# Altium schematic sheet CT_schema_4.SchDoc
size 573 x 363 mm
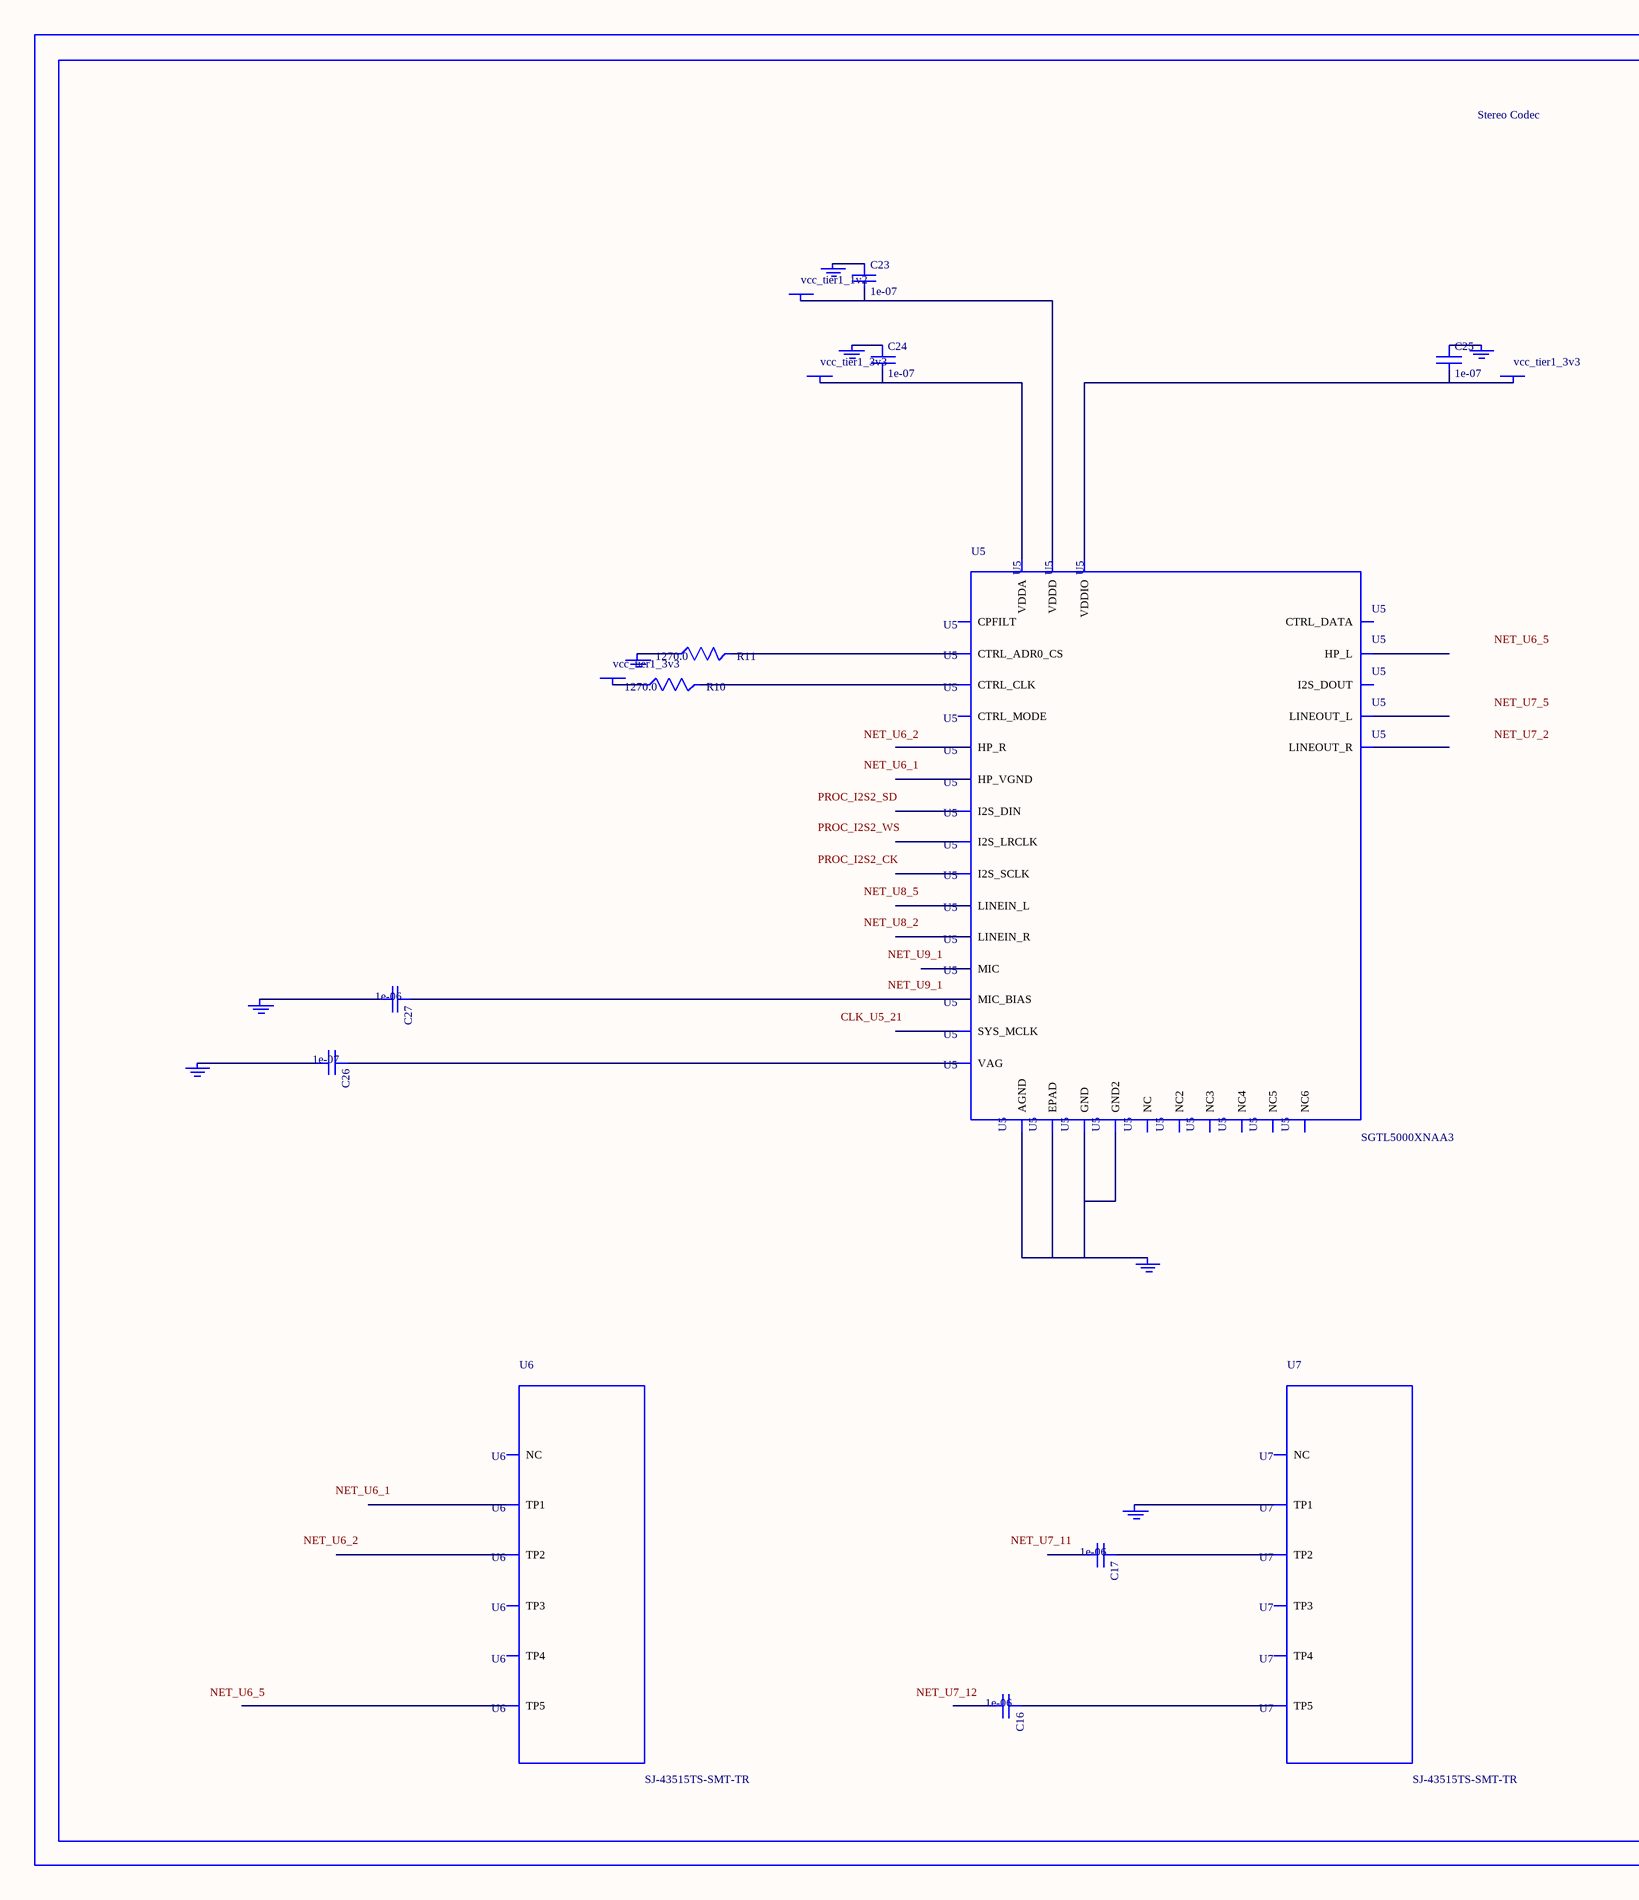
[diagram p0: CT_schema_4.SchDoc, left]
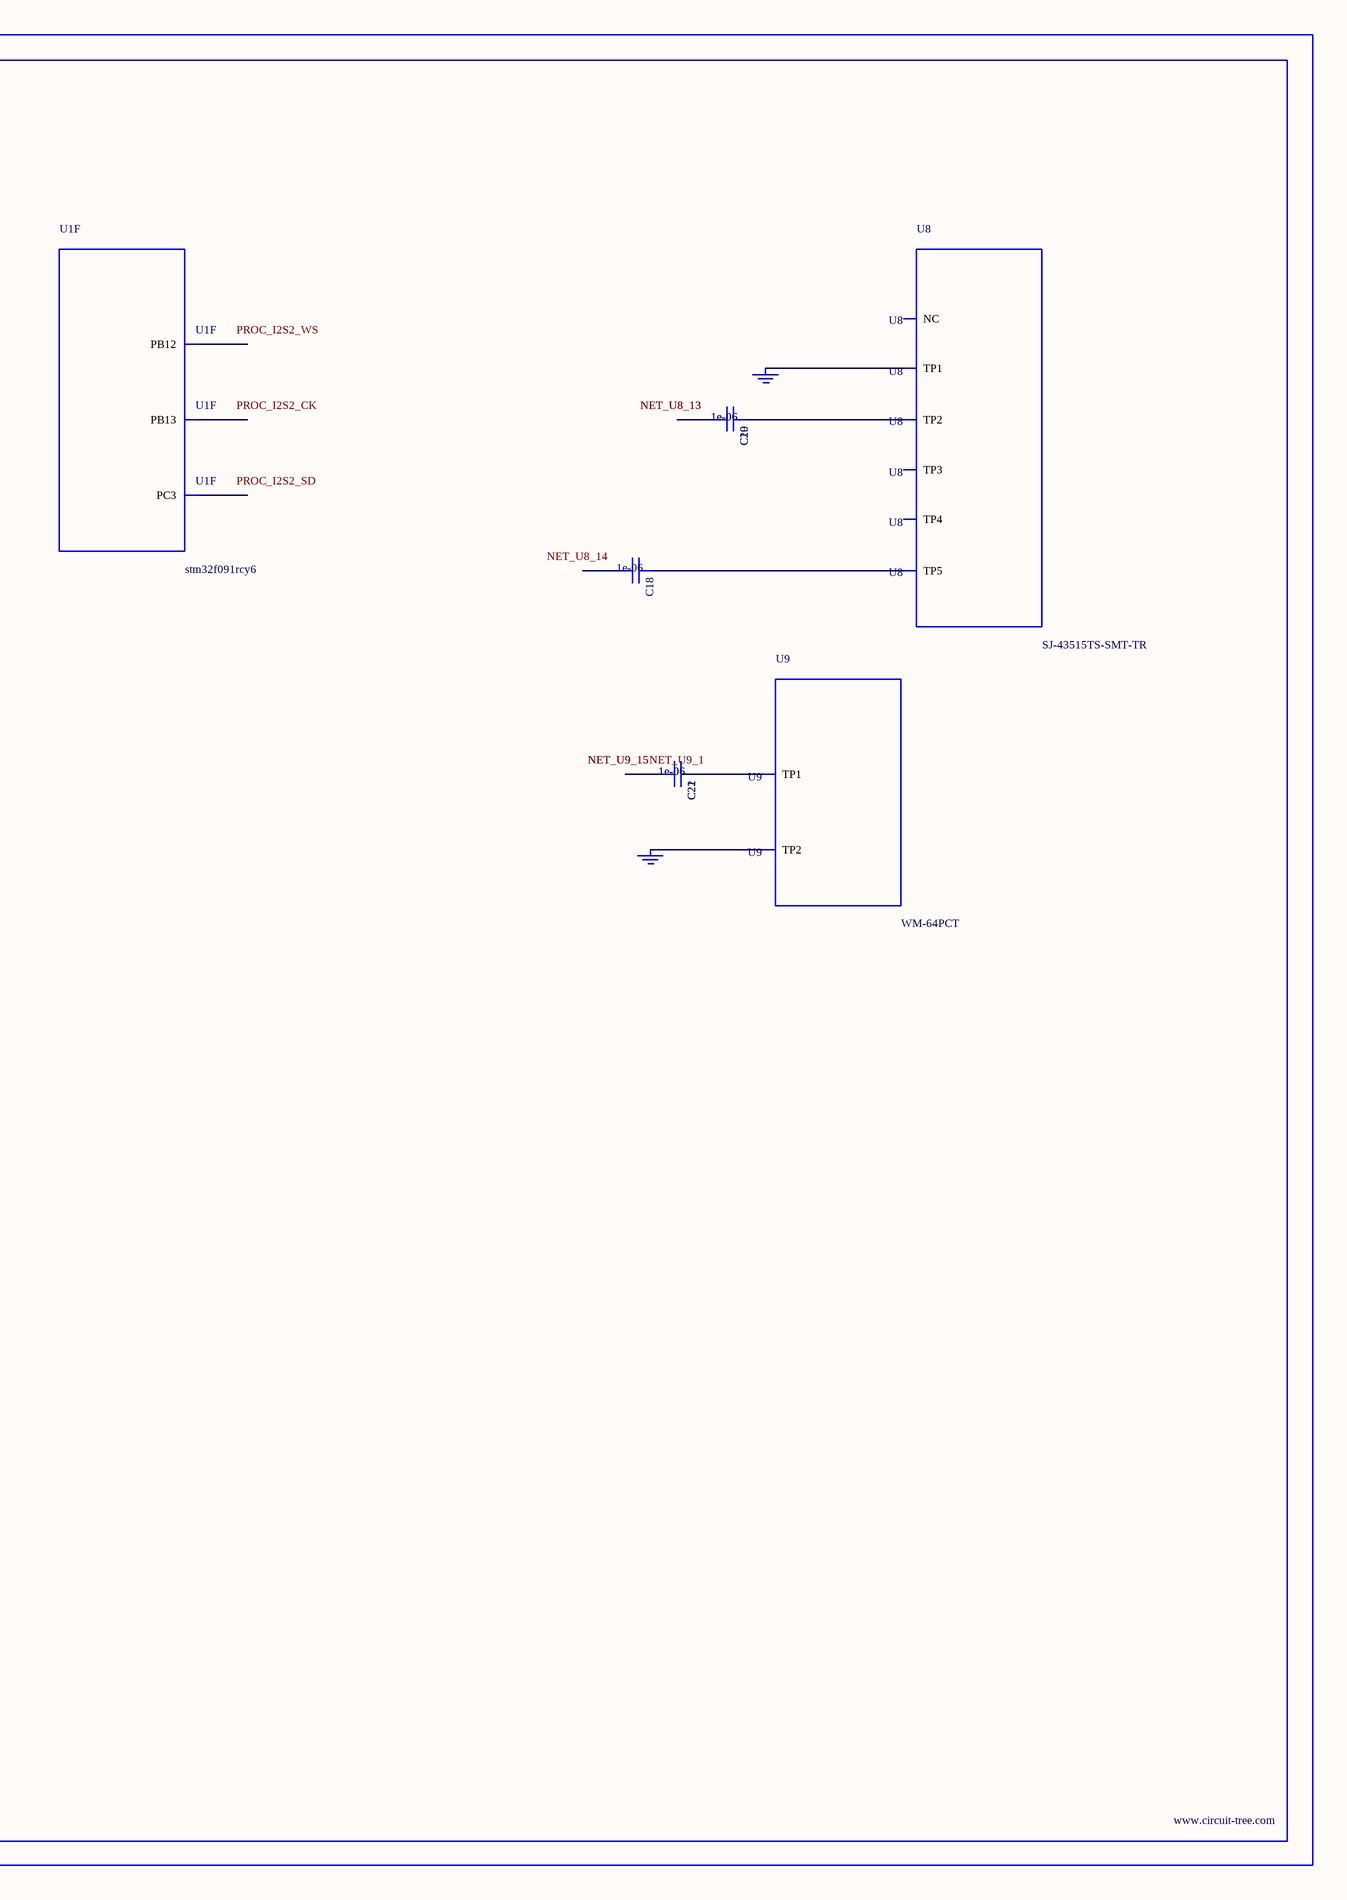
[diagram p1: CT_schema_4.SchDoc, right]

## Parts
BORDER3  (no value)
C16  1e-06  [C0603]
C17  1e-06  [C0603]
C18  1e-06  [C0603]
C19  1e-06  [C0603]
C20  1e-06  [C0603]
C21  1e-06  [C0603]
C22  1e-06  [C0603]
C23  1e-07  [C0402]
C24  1e-07  [C0402]
C25  1e-07  [C0402]
C26  1e-07  [C0402]
C27  1e-06  [C0603]
GND_INSTANCE_3_0  (no value)
GND_INSTANCE_3_1  (no value)
GND_INSTANCE_3_2  (no value)
GND_INSTANCE_3_3  (no value)
GND_INSTANCE_3_4  (no value)
GND_INSTANCE_3_5  (no value)
GND_INSTANCE_3_6  (no value)
GND_INSTANCE_3_7  (no value)
GND_INSTANCE_3_8  (no value)
GND_INSTANCE_3_9  (no value)
GND_INSTANCE_3_10  (no value)
POWER_INSTANCE_3_0  vcc_tier1_3v3
POWER_INSTANCE_3_1  vcc_tier1_3v3
POWER_INSTANCE_3_2  vcc_tier1_3v3
POWER_INSTANCE_3_3  vcc_tier1_1v2
R10  1270.0  [R0603]
R11  1270.0  [R0603]
U1  stm32f091rcy6  [WLCSP64]  (part F of 8)
U5  SGTL5000XNAA3  [QFN-32]
U6  SJ-43515TS-SMT-TR  [SJ-43515TS-SMT-TR]
U7  SJ-43515TS-SMT-TR  [SJ-43515TS-SMT-TR]
U8  SJ-43515TS-SMT-TR  [SJ-43515TS-SMT-TR]
U9  WM-64PCT  [WM-64PC]

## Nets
NetC16_1: C16.1 U7.5(TP5)
NetC17_1: C17.1 U7.2(TP2)
NetC18_1: C18.1 U8.5(TP5)
NetC19_1: C19.1 C20.1 U8.2(TP2)
NetC19_2: C19.2 C20.2
NetC21_1: C21.1 C22.1 U9.1(TP1)
NetC21_2: C21.2 C22.2
NetC23_1: C23.1 GND_INSTANCE_3_5.0(GND)
NetC23_2: C23.2 POWER_INSTANCE_3_3.0(PWR) U5.30(VDDD)
NetC24_1: C24.1 GND_INSTANCE_3_1.0(GND)
NetC24_2: C24.2 POWER_INSTANCE_3_0.0(PWR) U5.5(VDDA)
NetC25_1: C25.1 GND_INSTANCE_3_4.0(GND)
NetC25_2: C25.2 POWER_INSTANCE_3_1.0(PWR) U5.20(VDDIO)
NetC26_1: C26.1 U5.10(VAG)
NetC26_2: C26.2 GND_INSTANCE_3_2.0(GND)
NetC27_1: C27.1 U5.16(MIC_BIAS)
NetC27_2: C27.2 GND_INSTANCE_3_3.0(GND)
NetGND_INSTANCE_3_0_0: GND_INSTANCE_3_0.0(GND) U5.1(GND) U5.3(GND2) U5.7(AGND) U5.EXP(EPAD)
NetGND_INSTANCE_3_6_0: GND_INSTANCE_3_6.0(GND) R11.1
NetGND_INSTANCE_3_7_0: GND_INSTANCE_3_7.0(GND) U7.1(TP1)
NetGND_INSTANCE_3_8_0: GND_INSTANCE_3_8.0(GND) GND_INSTANCE_3_9.0(GND) U8.1(TP1)
NetGND_INSTANCE_3_10_0: GND_INSTANCE_3_10.0(GND) U9.2(TP2)
NetPOWER_INSTANCE_3_2_0: POWER_INSTANCE_3_2.0(PWR) R10.1
NetR10_2: R10.2 U5.29(CTRL_CLK)
NetR11_2: R11.2 U5.31(CTRL_ADR0_CS)

Not connected (* = marked no-connect by the designer): C16 2; C17 2; C18 2; U1 E6(PC3) F2(PB13) G2(PB12); U5 2(HP_R) 4(HP_VGND) 6(HP_L) 8(NC) 9(NC2) 11(LINEOUT_R) 12(LINEOUT_L) 13(LINEIN_R) 14(LINEIN_L) 15(MIC) 17(NC3) 18(CPFILT) 19(NC4) 21(SYS_MCLK) 22(NC5) 23(I2S_LRCLK) 24(I2S_SCLK) 25(I2S_DOUT) 26(I2S_DIN) 27(CTRL_DATA) 28(NC6) 32(CTRL_MODE); U6 1(TP1) 2(TP2) 3(TP3) 4(TP4) 5(TP5) 6(NC); U7 3(TP3) 4(TP4) 6(NC); U8 3(TP3) 4(TP4) 6(NC)

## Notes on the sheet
- Labels drawn without touching a wire or pin: CLK_U5_21, NET_U6_1, NET_U6_2, NET_U6_5, NET_U7_2, NET_U7_5, NET_U7_11, NET_U7_12, NET_U8_2, NET_U8_5, NET_U8_14, NET_U9_1, PROC_I2S2_CK, PROC_I2S2_SD, PROC_I2S2_WS

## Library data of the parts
BORDER3 = BORDER_PAGE3
C16-C22 C27 = C0603C105K3RACTU
C23-C26 = C0402C104K3RACTU
GND_INSTANCE_3_0-GND_INSTANCE_3_10 = GND
POWER_INSTANCE_3_0-POWER_INSTANCE_3_3 = PWR
R10 R11 = RC0603FR-071K27L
